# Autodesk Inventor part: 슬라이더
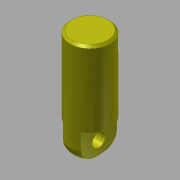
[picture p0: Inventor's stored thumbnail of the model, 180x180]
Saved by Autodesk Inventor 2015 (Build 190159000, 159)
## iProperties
Created: 2016-08
Part Number: 슬라이더
Material: 강철, 탄소
Document SubType Name: Modeling
Designer: mduedu
Density: 7.87 g/cm^3
Appearance: 노란색
Author: mduedu
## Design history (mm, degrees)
sketch "스케치1"
  geometry: C1 r 9 at (0, 0); 1 further point
  constraints: 1 centre point, 1 coincident
  dimensions: "d0" = 18 diameter of C1
extrude "돌출1" new body sketch "스케치1" distance "d1" = 47; taper "d2" = 0 deg
fillet "모깎기1" dims "d21" = 6
sketch "스케치6"
  geometry: L1 (9, 6)-(9, 47) reference; L2 (-9, 6)-(-9, 47) reference; L3 (9, 47)-(-9, 47) reference; L4 (0, 47)-(0, 0); L5 (9, 13)-(4, 13); L6 (4, 13)-(4, 0); L7 (4, 0)-(9, 0); L8 (9, 0)-(9, 13); L9 (-9, 13)-(-4, 13); L10 (-4, 13)-(-4, 0); L11 (-4, 0)-(-9, 0); L12 (-9, 0)-(-9, 13)
  constraints: 18 end point, 4 symmetric about line, 2 parallel, 2 perpendicular, 1 horizontal, 1 horizontal alignment, 1 midpoint, 1 point on line
  dimensions: "d22" = 13 distance of L7.end L5.start; "d24" = 4 distance between parallel lines of L6 L4
extrude "돌출5" cut sketch "스케치6" stored distance "d25" = 8; taper "d26" = 0 deg
sketch "스케치8"
  geometry: C1 r 3 at (6, 0); 1 further point
  constraints: 1 centre point, 1 horizontal alignment
  dimensions: "d27" = 6 diameter of C1; "d28" = 6 distance of point (0, 0) C1.centre
extrude "돌출6" cut sketch "스케치8" stored distance "d29" = 8; taper "d30" = 0 deg
chamfer "모따기2" distance "d43" = 1; stored, may be unused: second distance "d44" = 2, angle "d45" = 30 deg
node "솔리드1"
